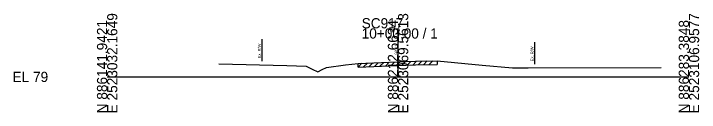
# Model space of a CAD drawing. Extents: x -26 to 218, y -10 to 12021.
# Drawn here: x -25.7 to 162.8, y 8990.3 to 9017.3 of the extents above; entities that cross this region are included whole.
import ezdxf

# ---------------------------------------------------------------- set-up
doc = ezdxf.new("R2010")
doc.units = 0
for name, color, linetype in [('RD_GPK_XS_Cell', 7, 'Continuous'), ('RD_XS_ExGround', 7, 'Continuous'), ('RD_XS_ExPaveRet', 7, 'Continuous'), ('RD_XS_ExRW', 7, 'Continuous'), ('RD_XS_TX_Elev_EX', 7, 'Continuous')]:
    doc.layers.add(name, color=color, linetype=linetype)

msp = doc.modelspace()

# ---------------------------------------------------------------- linework, layer by layer
at = {"layer": 'RD_GPK_XS_Cell'}
for p, q in [((80, 9000), (80, 9013.31)), ((0, 9000), (80, 9000)), ((80, 9000), (160, 9000))]:
    msp.add_line(p, q, dxfattribs=at)
at = {"layer": 'RD_XS_ExGround'}
for p, q in [((84.83, 9004.29), (90.78, 9004.44)), ((90.78, 9004.44), (103.1, 9003.23)), ((30.68, 9003.55), (49.45, 9003.16)), ((49.45, 9003.16), (54.73, 9002.92)), ((54.73, 9002.92), (56.34, 9002.13)), ((59.15, 9002), (60.32, 9002.58)), ((60.32, 9002.58), (65.56, 9003.28)), ((65.56, 9003.28), (69.02, 9003.71)), ((69.02, 9003.71), (75.44, 9003.93)), ((75.44, 9003.93), (79.8, 9004.1)), ((79.8, 9004.1), (84.83, 9004.29)), ((103.1, 9003.23), (111.43, 9002.46)), ((111.43, 9002.46), (115.79, 9002.51)), ((115.79, 9002.51), (152.4, 9002.59)), ((56.34, 9002.13), (57.92, 9001.41)), ((57.92, 9001.41), (59.15, 9002))]:
    msp.add_line(p, q, dxfattribs=at)
at = {"layer": 'RD_XS_ExPaveRet'}
for p, q in [((85.52, 9003.3), (86.55, 9004.33)), ((87.02, 9003.34), (88.05, 9004.37)), ((88.52, 9003.38), (89.55, 9004.41)), ((90.78, 9004.44), (90.78, 9003.44)), ((69.02, 9002.71), (70.06, 9003.75)), ((69.02, 9002.71), (69.02, 9003.71)), ((69.02, 9002.71), (75.44, 9002.93)), ((70.52, 9002.77), (71.56, 9003.8)), ((72.02, 9002.82), (73.06, 9003.85)), ((73.52, 9002.87), (74.56, 9003.9)), ((75.02, 9002.92), (76.06, 9003.96)), ((75.44, 9002.93), (79.8, 9003.1)), ((76.52, 9002.97), (77.56, 9004.01)), ((78.02, 9003.03), (79.06, 9004.07)), ((79.52, 9003.09), (80.56, 9004.13)), ((79.8, 9003.1), (84.83, 9003.29)), ((81.02, 9003.14), (82.06, 9004.18)), ((82.52, 9003.2), (83.56, 9004.24)), ((84.02, 9003.26), (85.06, 9004.29)), ((84.83, 9003.29), (90.78, 9003.44))]:
    msp.add_line(p, q, dxfattribs=at)
at = {"layer": 'RD_XS_ExRW'}
for p, q in [((42.5, 9010.31), (42.5, 9004.31)), ((117.5, 9009.51), (117.5, 9003.51)), ((117.5, 9009.51), (117.5, 9003.51))]:
    msp.add_line(p, q, dxfattribs=at)

# ---------------------------------------------------------------- texts
at = {"layer": 'RD_GPK_XS_Cell'}
for s, p in [('E 2523032.1649', (2.8, 8990)), ('E 2523069.5613', (82.8, 8990)), ('E 2523106.9577', (162.8, 8990)), ('N 886141.9421', (0, 8990)), ('N 886212.6634', (80, 8990)), ('N 886283.3848', (160, 8990))]:
    msp.add_text(s, height=2.8, rotation=90, dxfattribs=at).set_placement(p)
for s, p in [('SC917', (70, 9013.31)), ('10+00.00 / 1', (70, 9010.51)), ('EL 79', (-26, 8998.6))]:
    msp.add_text(s, height=2.8, dxfattribs=at).set_placement(p)
at = {"layer": 'RD_XS_ExRW'}
for p in [(42.25, 9005.09), (117.25, 9004.3), (117.25, 9004.3)]:
    msp.add_text('Ex. R/W ', height=0.8, rotation=90, dxfattribs=at).set_placement(p)
at = {"layer": 'RD_XS_TX_Elev_EX'}
msp.add_text('83.11', height=0.8, rotation=90, dxfattribs=at).set_placement((79.9, 9006.11))

doc.saveas('drawing.dxf')
